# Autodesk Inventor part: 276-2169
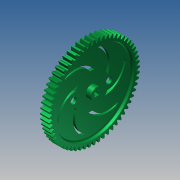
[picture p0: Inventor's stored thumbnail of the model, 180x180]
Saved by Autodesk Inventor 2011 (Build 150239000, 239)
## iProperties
Created: 2010-06
Part Number: 276-2169
Material: Steel
Document SubType Name: Modeling
Designer: Autodesk Inc.
Categories: <?xml version="1.0" encoding="UTF-16"?> <MemberInstance><Categories><FamilyTemplate><FamilyTemplateParameter ValueType="xs:double" Id="1" ObjectReferenceKey="da
Density: 1 g/cm^3
Catalog Web Link: http://www.vexrobotics.com/products/accessories/motion/276-2169.html
Description: This kit contains four sizes of VEX Spur Gears (12-, 36-, 60-, and 84-tooth gears). The 60- and 84-tooth gears have extra mount
Vendor: Innovation First, Inc.
CustomPartVersion: 1
Company: Autodesk Inc.
Author: Autodesk Inc.
Title: VEX Robotics Kit of Parts
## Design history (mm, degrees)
sketch "Sketch1"
  geometry: C1 r 32.597 at (0, 0)
  constraints: 1 centre point
  dimensions: "d0" = 65.19333 diameter of C1 (= da_da)
extrude "Extrusion1" new body sketch "Sketch1" distance "d1" = 6.35 (= da_b); taper "d2" = 0 deg
sketch "Sketch2"
  geometry: C1 r 32.597 at (0, 0) reference; C2 r 31.75 at (0, 0)
  constraints: 1 centre point, 1 coincident
  dimensions: "d3" = 63.5 diameter of C2 (= da_dw)
feature "Pitch Diameter" sketch "Sketch2" dims "d4" = 76.2, "d5" = 0
workplane "Work Plane1"
workplane "Work Plane2"
workplane "Work Plane3"
feature "Spur Gear" dims "da_b" = 6.35, "da_d" = 63.5, "da_aw" = 38.1, "da_da" = 65.19333, "da_df" = 60.43083, "da_dw" = 63.5, angle "da_beta" = 0 deg, "da_lefttooth" = 0, "da_righttooth" = 0
sketch "Sketch4"
  geometry: C1 r 28.613 at (0, 0); A1 r 32.597 centre (0, 0) between (-2.983, 32.46) and (-3.831, 32.371) reference
  constraints: 1 centre point, 1 coincident
  dimensions: "d20" = 57.2262 diameter of C1
extrude "Extrusion2" cut sketch "Sketch4" distance "d21" = 2.1844; taper "d22" = 0 deg
fillet "Fillet1" dims "d23" = 0.9906
workplane "Work Plane4"
mirror "Mirror1"
sketch "Sketch5"
  geometry: C1 r 4 at (0, 0); C2 r 2.175 at (12.7, 0); C3 r 2.175 at (-12.7, 0); A1 r 12.583 centre (0, 0) between (11.762, 4.47) and (10.329, 7.185); A2 r 12.583 centre (0, 0) between (2.01, 12.421) and (-1.058, 12.538); A3 r 25.267 centre (0, 0) between (6.804, 24.334) and (4.537, 24.857); A4 r 12.583 centre (0, 0) between (-2.01, -12.421) and (1.058, -12.538); A5 r 25.267 centre (0, 0) between (17.672, -18.059) and (19.258, -16.357); A6 r 25.267 centre (0, 0) between (24.476, 6.275) and (23.795, 8.499); A7 r 12.583 centre (0, 0) between (9.752, -7.951) and (11.387, -5.353); A8 r 25.267 centre (0, 0) between (-17.672, 18.059) and (-19.258, 16.357); A9 r 12.583 centre (0, 0) between (-9.752, 7.951) and (-11.387, 5.353); A10 r 12.583 centre (0, 0) between (-11.762, -4.47) and (-10.329, -7.185); A11 r 25.267 centre (0, 0) between (-24.476, -6.275) and (-23.795, -8.499); A12 r 25.267 centre (0, 0) between (-6.804, -24.334) and (-4.537, -24.857)
  constraints: 24 point on circle, 15 centre point, 24 other
extrude "Extrusion3" cut sketch "Sketch5" stored distance "d24" = 5.7531; taper "d25" = 0 deg
extrude "Extrusion4" join sketch "Sketch5" distance "d26" = 3.7592; taper "d27" = 0 deg
mirror "Mirror2"
sketch "Sketch6"
  geometry: L1 (1.612, 0.952)-(1.558, 1.007); L2 (1.558, 1.025)-(1.612, 1.079); L3 (1.612, 1.104)-(1.612, 1.079); L4 (1.558, 1.177)-(1.612, 1.231); L5 (1.612, 1.362)-(1.612, 1.231); L6 (1.232, 1.612)-(1.177, 1.558); L7 (1.159, 1.558)-(1.105, 1.612); L8 (1.079, 1.612)-(1.105, 1.612); L9 (1.232, 1.612)-(1.362, 1.612); L10 (1.612, 0.952)-(1.612, -0.952); L11 (1.558, -1.007)-(1.612, -0.952); L12 (1.612, 1.104)-(1.558, 1.159); L13 (1.079, 1.612)-(1.025, 1.558); L14 (-1.362, 1.612)-(-1.231, 1.612); L15 (-1.177, 1.558)-(-1.231, 1.612); L16 (1.007, 1.558)-(0.952, 1.612); L17 (-0.952, 1.613)-(0.952, 1.612); L18 (-0.952, 1.613)-(-1.007, 1.558); L19 (-1.024, 1.558)-(-1.079, 1.612); L20 (-1.104, 1.613)-(-1.079, 1.612); L21 (-1.104, 1.613)-(-1.159, 1.558); L22 (1.613, -1.079)-(1.558, -1.024); L23 (1.613, -1.079)-(1.612, -1.105); L24 (1.558, -1.159)-(1.612, -1.105); L25 (1.613, -1.231)-(1.558, -1.177); L26 (1.613, -1.231)-(1.612, -1.362); L27 (1.362, -1.612)-(1.231, -1.612); L28 (1.177, -1.558)-(1.231, -1.612); L29 (1.104, -1.613)-(1.079, -1.612); L30 (1.024, -1.558)-(1.079, -1.612); L31 (0.952, -1.613)-(1.007, -1.558); L32 (0.952, -1.613)-(-0.952, -1.612); L33 (1.104, -1.613)-(1.159, -1.558); L34 (-1.007, -1.558)-(-0.952, -1.612); L35 (-1.079, -1.612)-(-1.025, -1.558); L36 (-1.079, -1.612)-(-1.105, -1.612); L37 (-1.159, -1.558)-(-1.105, -1.612); L38 (-1.232, -1.612)-(-1.177, -1.558); L39 (-1.612, -0.952)-(-1.558, -1.007); L40 (-1.558, -1.025)-(-1.612, -1.079); L41 (-1.612, -1.104)-(-1.612, -1.079); L42 (-1.612, -1.104)-(-1.558, -1.159); L43 (-1.558, -1.177)-(-1.612, -1.231); L44 (-1.612, -1.362)-(-1.612, -1.231); L45 (-1.232, -1.612)-(-1.362, -1.612); L46 (-1.612, -0.952)-(-1.612, 0.952); L47 (-1.558, 1.007)-(-1.612, 0.952); L48 (-1.613, 1.079)-(-1.558, 1.024); L49 (-1.613, 1.079)-(-1.612, 1.105); L50 (-1.558, 1.159)-(-1.612, 1.105); L51 (-1.613, 1.231)-(-1.558, 1.177); L52 (-1.613, 1.231)-(-1.612, 1.362); A1 r 0.013 centre (1.567, 1.016) between (1.558, 1.025) and (1.558, 1.007); A2 r 0.013 centre (1.567, 1.168) between (1.558, 1.177) and (1.558, 1.159); A3 r 0.25 centre (1.362, 1.362) between (1.612, 1.362) and (1.362, 1.612); A4 r 0.013 centre (1.168, 1.567) between (1.159, 1.558) and (1.177, 1.558); A5 r 0.012 centre (-1.016, 1.566) between (-1.024, 1.558) and (-1.007, 1.558); A6 r 0.012 centre (-1.168, 1.566) between (-1.177, 1.558) and (-1.159, 1.558); A7 r 0.013 centre (1.016, 1.567) between (1.007, 1.558) and (1.025, 1.558); A8 r 0.012 centre (1.566, -1.016) between (1.558, -1.007) and (1.558, -1.024); A9 r 0.013 centre (1.567, -1.168) between (1.558, -1.159) and (1.558, -1.177); A10 r 0.25 centre (1.362, -1.362) between (1.362, -1.612) and (1.612, -1.362); A11 r 0.012 centre (1.168, -1.566) between (1.177, -1.558) and (1.159, -1.558); A12 r 0.012 centre (1.016, -1.566) between (1.024, -1.558) and (1.007, -1.558); A13 r 0.013 centre (-1.016, -1.567) between (-1.007, -1.558) and (-1.025, -1.558); A14 r 0.013 centre (-1.168, -1.567) between (-1.159, -1.558) and (-1.177, -1.558); A15 r 0.013 centre (-1.567, -1.168) between (-1.558, -1.177) and (-1.558, -1.159); A16 r 0.013 centre (-1.567, -1.016) between (-1.558, -1.025) and (-1.558, -1.007); A17 r 0.25 centre (-1.362, -1.362) between (-1.612, -1.362) and (-1.362, -1.612); A18 r 0.25 centre (-1.362, 1.362) between (-1.362, 1.612) and (-1.612, 1.362); A19 r 0.013 centre (-1.567, 1.168) between (-1.558, 1.159) and (-1.558, 1.177); A20 r 0.012 centre (-1.566, 1.016) between (-1.558, 1.007) and (-1.558, 1.024); 1 further point
  constraints: 104 end point, 40 point on circle, 20 centre point
feature "iFeature2:1" sketch "Sketch6"
body "Solid1"
body "Srf1"
other parameters: "d6" = 0, "d7" = 3 deg (computed from da_z), "d9" = 0, "d14" = 0, "d15" = 38.1 (= da_aw), "d16" = 0, "d17" = 0, "d18" = 0, "d19" = 38.1 (= da_aw)
